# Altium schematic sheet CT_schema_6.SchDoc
size 368 x 245 mm
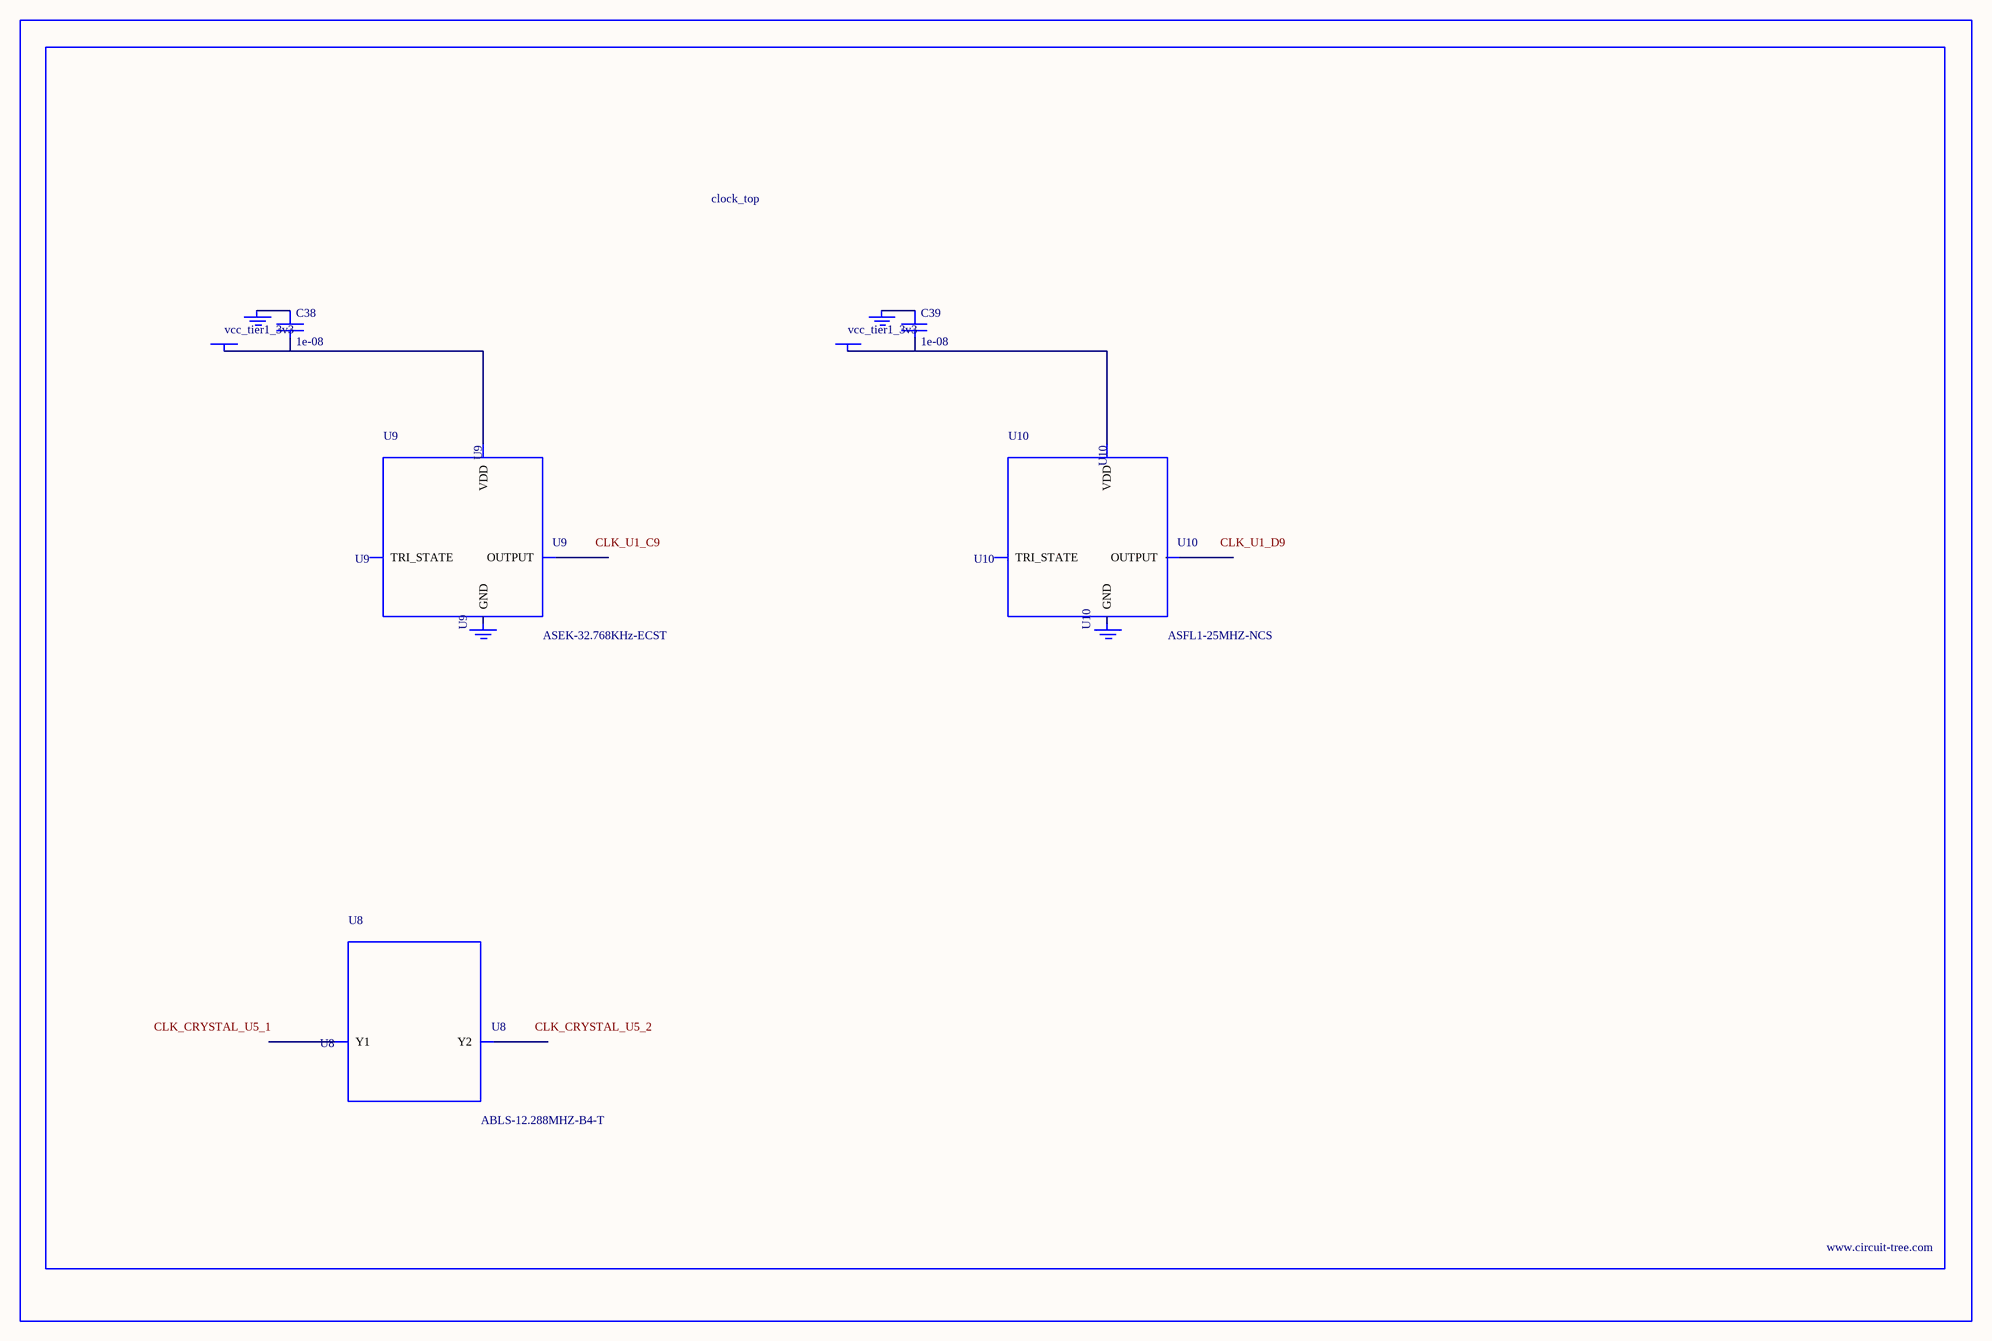
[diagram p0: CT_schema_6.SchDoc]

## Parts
BORDER5  (no value)
C38  1e-08  [C0402]
C39  1e-08  [C0402]
GND_INSTANCE_5_0  (no value)
GND_INSTANCE_5_1  (no value)
GND_INSTANCE_5_2  (no value)
GND_INSTANCE_5_3  (no value)
POWER_INSTANCE_5_0  vcc_tier1_3v3
POWER_INSTANCE_5_1  vcc_tier1_3v3
U8  ABLS-12.288MHZ-B4-T  [ABLS-12.288MHZ-B4-T]
U9  ASEK-32.768KHz-ECST  [ASEK]
U10  ASFL1-25MHZ-NCS  [ASFL1]

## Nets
NetC38_1: C38.1 GND_INSTANCE_5_0.0(GND)
NetC38_2: C38.2 POWER_INSTANCE_5_0.0(PWR) U9.4(VDD)
NetC39_1: C39.1 GND_INSTANCE_5_2.0(GND)
NetC39_2: C39.2 POWER_INSTANCE_5_1.0(PWR) U10.4(VDD)

Not connected (* = marked no-connect by the designer): GND_INSTANCE_5_1 0(GND); GND_INSTANCE_5_3 0(GND); U8 1(Y1) 2(Y2); U9 1(TRI_STATE) 2(GND) 3(OUTPUT); U10 1(TRI_STATE) 2(GND) 3(OUTPUT)

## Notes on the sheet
- Labels drawn without touching a wire or pin: CLK_CRYSTAL_U5_1, CLK_CRYSTAL_U5_2, CLK_U1_C9, CLK_U1_D9

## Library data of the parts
BORDER5 = BORDER_PAGE5
C38 C39 = C0402C103K3RAC
GND_INSTANCE_5_0-GND_INSTANCE_5_3 = GND
POWER_INSTANCE_5_0 POWER_INSTANCE_5_1 = PWR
